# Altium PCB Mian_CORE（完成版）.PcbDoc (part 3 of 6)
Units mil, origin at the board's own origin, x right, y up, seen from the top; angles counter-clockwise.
Board outline 2755.91 x 1771.65 mil, 4 copper layers (TOP, GND02, PWR03, BOTTOM); 61 components, 130 nets, 4907 pads, 497 vias.
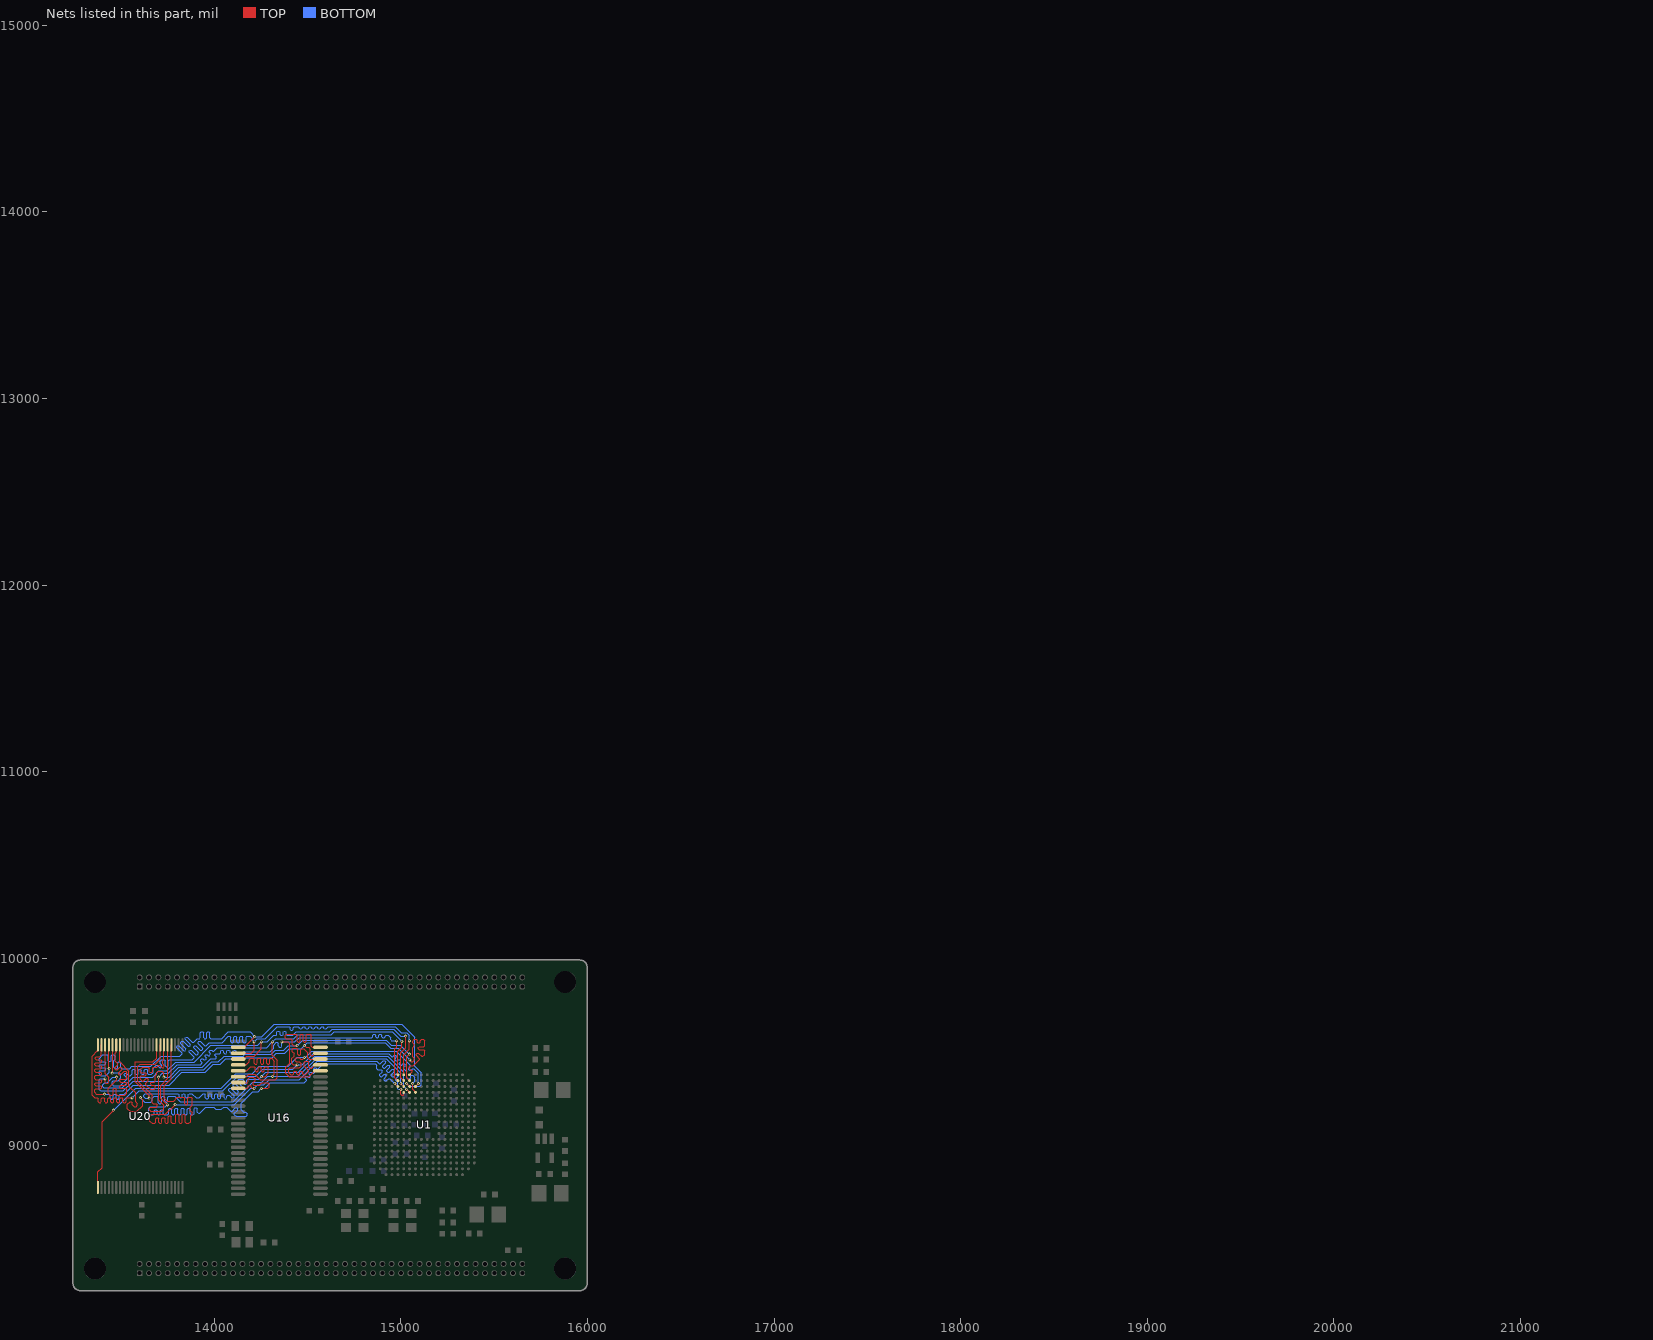
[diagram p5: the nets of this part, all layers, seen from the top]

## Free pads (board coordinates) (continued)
  round 8 on Drill Drawing: 1(18151.23,8951.1) 1(18151.23,8951.1) 1(18151.23,9026.1) 1(18151.23,9026.1) 1(18169.89,8951.1) 1(18169.89,8951.1) 1(18169.89,9026.1) 1(18169.89,9026.1) 1(18177.36,8954.85) 1(18177.36,8954.85) 1(18177.36,9022.35) 1(18177.36,9022.35) 1(18182.96,8959.85) 1(18182.96,8959.85) 1(18182.96,9017.35) 1(18182.96,9017.35) 1(18187.63,8967.35) 1(18187.63,8967.35) 1(18187.63,9009.85) 1(18187.63,9009.85) 1(18191.36,8976.1) 1(18191.36,8976.1) 1(18191.36,9001.1) 1(18191.36,9001.1) 1(18192.29,8988.6) 1(18192.29,8988.6) 1(18235.56,8951.1) 1(18235.56,9026.1) 1(18246.76,8951.1) 1(18246.76,9026.1) 1(18257.96,8951.1) 1(18257.96,9026.1) 1(18304.03,8951.1) 1(18304.03,8989.85) 1(18304.03,9026.1) 1(18304.03,9026.1) 1(18326.43,8989.85) 1(18339.49,9026.1) 1(18352.8,9563.73) 1(18356.53,9609.98) 1(18356.53,9609.98) 1(18358.4,9618.73) 1(18358.4,9618.73) 1(18359.33,9601.23) 1(18359.33,9601.23) 1(18360.27,9557.48) 1(18360.27,9557.48) 1(18363.07,9624.98) 1(18363.07,9624.98) 1(18365.87,9596.23) 1(18365.87,9596.23) 1(18368.67,9553.73) 1(18368.67,9553.73) 1(18369.6,9628.73) 1(18369.6,9628.73) 1(18376.13,9553.73) 1(18376.13,9553.73) 1(18376.13,9628.73) 1(18376.13,9628.73) 1(18377.07,9593.73) 1(18377.07,9593.73) 1(18379.03,8951.1) 1(18379.03,8989.85) 1(18379.03,9026.1) 1(18379.03,9026.1) 1(18382.67,9626.23) 1(18382.67,9626.23) 1(18383.6,9557.48) 1(18383.6,9557.48) 1(18385.47,9588.73) 1(18385.47,9588.73) 1(18388.27,9619.98) 1(18389.2,9563.73) 1(18389.2,9563.73) 1(18390.13,9581.23) 1(18390.13,9581.23) 1(18392,9572.48) 1(18392,9572.48) 1(18401.43,8989.85) 1(18414.49,9026.1) 1(18436.2,9553.73) 1(18436.2,9628.73) 1(18447.4,9553.73) 1(18447.4,9628.73) 1(18453.09,8951.1) 1(18453.09,8951.1) 1(18453.09,8989.85) 1(18453.09,9026.1) 1(18453.09,9026.1) 1(18458.6,9553.73) 1(18458.6,9628.73) 1(18475.49,8989.85) 1(18490.43,8951.1) 1(18490.43,9026.1) 1(18500.93,9553.73) 1(18500.93,9628.73) 1(18500.93,9628.73) 1(18528.09,8951.1) 1(18528.09,8987.35) 1(18528.09,9026.1) 1(18528.09,9026.1) 1(18543.87,9553.73) 1(18543.87,9553.73) 1(18543.87,9628.73) 1(18551.43,8987.35) 1(18551.43,8987.35) 1(18551.43,8987.35) 1(18551.43,9026.1) 1(18551.43,9026.1) 1(18557.96,8991.1) 1(18557.96,8991.1) 1(18558.89,9022.35) 1(18558.89,9022.35) 1(18563.56,8997.35) 1(18563.56,8997.35) 1(18563.56,9017.35) 1(18563.56,9017.35) 1(18565.43,8951.1) 1(18565.43,9007.35) 1(18565.43,9007.35) 1(18573.13,9587.48) 1(18573.13,9587.48) 1(18573.13,9596.23) 1(18573.13,9596.23) 1(18575,9577.48) 1(18575,9577.48) 1(18575,9603.73) 1(18575,9603.73) 1(18578.73,9568.73) 1(18578.73,9568.73) 1(18578.73,9612.48) 1(18578.73,9612.48) 1(18584.33,9561.23) 1(18584.33,9561.23) 1(18584.33,9619.98) 1(18584.33,9619.98) 1(18589.93,9624.98) 1(18589.93,9624.98) 1(18590.87,9556.23) 1(18590.87,9556.23) 1(18597.4,9628.73) 1(18597.4,9628.73) 1(18600.2,9553.73) 1(18600.2,9553.73) 1(18603,9591.23) 1(18603.09,8951.1) 1(18603.09,8951.1) 1(18603.09,8989.85) 1(18603.09,9026.1) 1(18603.09,9026.1) 1(18603.93,9628.73) 1(18603.93,9628.73) 1(18609.53,9556.23) 1(18609.53,9556.23) 1(18611.4,9626.23) 1(18611.4,9626.23) 1(18616.07,9561.23) 1(18616.07,9561.23) 1(18617,9621.23) 1(18621.67,9568.73) 1(18621.67,9568.73) 1(18621.67,9591.23) 1(18621.67,9591.23) 1(18625.49,8989.85) 1(18640.43,8951.1) 1(18640.43,9026.1) 1(18653.73,9553.73) 1(18653.73,9553.73) 1(18653.73,9628.73) 1(18675.29,8951.1) 1(18675.29,9026.1) 1(18675.29,9026.1) 1(18691.07,9553.73) 1(18718.23,8951.1) 1(18718.23,8951.1) 1(18718.23,9026.1) 1(18728.73,9553.73) 1(18728.73,9553.73) 1(18728.73,9592.48) 1(18728.73,9628.73) 1(18728.73,9628.73) 1(18750.29,9026.1) 1(18751.13,9592.48) 1(18766.07,9553.73) 1(18766.07,9628.73) 1(18771.76,8951.1) 1(18771.76,9026.1) 1(18793.23,9026.1) 1(18835.56,9026.1) 1(18846.76,8951.1) 1(18846.76,9026.1) 1(18857.96,9026.1) 1(18875.93,9628.73) 1(18897.37,8938.89) 1(18897.4,9553.73) 1(18897.4,9628.73) 1(18898.43,8951.1) 1(18906.83,8977.35) 1(18918.87,9628.73) 1(18919.77,8938.89) 1(18921.76,9026.1) 1(18921.76,9026.1) 1(18936.69,8977.35) 1(18945.09,8951.1) 1(18953.73,9553.73) 1(18953.73,9589.98) 1(18953.73,9628.73) 1(18953.73,9628.73) 1(18977.07,9589.98) 1(18977.07,9589.98) 1(18977.07,9589.98) 1(18977.07,9628.73) 1(18977.07,9628.73) 1(18978.09,8951.1) 1(18978.09,8951.1) 1(18978.09,9026.1) 1(18983.6,9593.73) 1(18983.6,9593.73) 1(18984.53,9624.98) 1(18984.53,9624.98) 1(18989.2,9599.98) 1(18989.2,9599.98) 1(18989.2,9619.98) 1(18989.2,9619.98) 1(18991.07,9553.73) 1(18991.07,9609.98) 1(18991.07,9609.98) 1(19015.43,8951.1) 1(19024.07,9553.73) 1(19032.47,9579.98) 1(19047.4,9628.73) 1(19047.4,9628.73) 1(19062.33,9579.98) 1(19070.73,9553.73) 1(19099.07,9587.48) 1(19099.07,9587.48) 1(19100,9598.73) 1(19100,9598.73) 1(19100.93,9576.23) 1(19100.93,9576.23) 1(19103.73,9568.73) 1(19103.73,9568.73) 1(19103.73,9611.23) 1(19103.73,9611.23) 1(19108.4,9618.73) 1(19108.4,9618.73) 1(19109.33,9561.23) 1(19109.33,9561.23) 1(19114.93,9624.98) 1(19114.93,9624.98) 1(19115.87,9556.23) 1(19115.87,9556.23) 1(19122.4,9553.73) 1(19122.4,9553.73) 1(19123.33,9628.73) 1(19123.33,9628.73) 1(19125.29,9026.1) 1(19128.93,9553.73) 1(19128.93,9553.73) 1(19130.8,9628.73) 1(19130.8,9628.73) 1(19135.47,9556.23) 1(19135.47,9556.23) 1(19137.33,9626.23) 1(19137.33,9626.23) 1(19141.07,9559.98) 1(19141.07,9559.98) 1(19142.93,9622.48) 1(19145.73,9564.98) 1(19146.76,8951.1) 1(19146.76,9026.1) 1(19168.23,9026.1) 1(19178.73,9553.73) 1(19178.73,9553.73) 1(19178.73,9592.48) 1(19178.73,9628.73) 1(19178.73,9628.73) 1(19201.13,9592.48) 1(19203.09,8951.1) 1(19203.09,8987.35) 1(19203.09,9026.1) 1(19203.09,9026.1) 1(19216.07,9553.73) 1(19216.07,9628.73) 1(19226.43,8987.35) 1(19226.43,8987.35) 1(19226.43,8987.35) 1(19226.43,9026.1) 1(19226.43,9026.1) 1(19232.96,8991.1) 1(19232.96,8991.1) 1(19233.89,9022.35) 1(19233.89,9022.35) 1(19238.56,8997.35) 1(19238.56,8997.35) 1(19238.56,9017.35) 1(19238.56,9017.35) 1(19240.43,8951.1) 1(19240.43,9007.35) 1(19240.43,9007.35) 1(19273.43,8951.1) 1(19281.83,8977.35) 1(19296.76,9026.1) 1(19296.76,9026.1) 1(19311.69,8977.35) 1(19320.09,8951.1) 1(19336.2,9553.73) 1(19336.2,9628.73) 1(19347.4,9553.73) 1(19347.4,9628.73) 1(19348.43,8984.85) 1(19348.43,8984.85) 1(19349.36,8996.1) 1(19349.36,8996.1) 1(19350.29,8973.6) 1(19350.29,8973.6) 1(19353.09,8966.1) 1(19353.09,8966.1) 1(19353.09,9008.6) 1(19353.09,9008.6) 1(19357.76,9016.1) 1(19357.76,9016.1) 1(19358.6,9553.73) 1(19358.6,9628.73) 1(19358.69,8958.6) 1(19358.69,8958.6) 1(19364.29,9022.35) 1(19364.29,9022.35) 1(19365.23,8953.6) 1(19365.23,8953.6) 1(19371.76,8951.1) 1(19371.76,8951.1) 1(19372.69,9026.1) 1(19372.69,9026.1) 1(19378.29,8951.1) 1(19378.29,8951.1) 1(19380.16,9026.1) 1(19380.16,9026.1) 1(19384.83,8953.6) 1(19384.83,8953.6) 1(19386.69,9023.6) 1(19386.69,9023.6) 1(19390.43,8957.35) 1(19390.43,8957.35) 1(19392.29,9019.85) 1(19395.09,8962.35) 1(19398.13,9553.73) 1(19398.13,9628.73) 1(19398.13,9628.73) 1(19422.4,9566.23) 1(19422.4,9566.23) 1(19428.09,8951.1) 1(19428.09,8951.1) 1(19428.09,8989.85) 1(19428.09,9026.1) 1(19428.09,9026.1) 1(19446.67,9553.73) 1(19446.67,9628.73) 1(19446.67,9628.73) 1(19450.49,8989.85) 1(19465.43,8951.1) 1(19465.43,9026.1) 1(19478.73,9553.73) 1(19478.73,9584.98) 1(19478.73,9628.73) 1(19478.73,9628.73) 1(19501.13,9584.98) 1(19501.13,9584.98) 1(19501.13,9628.73) 1(19501.13,9628.73) 1(19508.6,9624.98) 1(19508.6,9624.98) 1(19509.53,9588.73) 1(19509.53,9588.73) 1(19514.2,9596.23) 1(19514.2,9596.23) 1(19514.2,9616.23) 1(19514.2,9616.23) 1(19516.07,9606.23) 1(19516.07,9606.23) 1(19553.73,9553.73) 1(19553.73,9553.73) 1(19553.73,9592.48) 1(19553.73,9628.73) 1(19553.73,9628.73) 1(19576.13,9592.48) 1(19585.56,8951.1) 1(19585.56,9026.1) 1(19591.07,9553.73) 1(19591.07,9628.73) 1(19596.76,8951.1) 1(19596.76,9026.1) 1(19607.96,8951.1) 1(19607.96,9026.1) 1(19626.87,9553.73) 1(19626.87,9553.73) 1(19626.87,9628.73) 1(19626.87,9628.73) 1(19645.53,9553.73) 1(19645.53,9553.73) 1(19645.53,9628.73) 1(19645.53,9628.73) 1(19647.49,8951.1) 1(19647.49,9026.1) 1(19647.49,9026.1) 1(19653,9557.48) 1(19653,9557.48) 1(19653,9624.98) 1(19653,9624.98) 1(19658.6,9562.48) 1(19658.6,9562.48) 1(19658.6,9619.98) 1(19658.6,9619.98) 1(19663.27,9569.98) 1(19663.27,9569.98) 1(19663.27,9612.48) 1(19663.27,9612.48) 1(19667,9578.73) 1(19667,9578.73) 1(19667,9603.73) 1(19667,9603.73) 1(19667.93,9591.23) 1(19667.93,9591.23) 1(19671.76,8963.6) 1(19671.76,8963.6) 1(19696.03,8951.1) 1(19696.03,9026.1) 1(19696.03,9026.1) 1(19699.07,9553.73) 1(19707.47,9579.98) 1(19722.4,9628.73) 1(19722.4,9628.73) 1(19728.09,8951.1) 1(19728.09,8982.35) 1(19728.09,9026.1) 1(19728.09,9026.1) 1(19737.33,9579.98) 1(19745.73,9553.73) 1(19750.49,8982.35) 1(19750.49,8982.35) 1(19750.49,9026.1) 1(19750.49,9026.1) 1(19757.96,9022.35) 1(19757.96,9022.35) 1(19758.89,8986.1) 1(19758.89,8986.1) 1(19763.56,8993.6) 1(19763.56,8993.6) 1(19763.56,9013.6) 1(19763.56,9013.6) 1(19765.43,9003.6) 1(19765.43,9003.6) 1(19775.93,9553.73) 1(19775.93,9628.73) 1(19775.93,9628.73) 1(19803.09,8951.1) 1(19803.09,8951.1) 1(19803.09,8989.85) 1(19803.09,9026.1) 1(19803.09,9026.1) 1(19818.87,9553.73) 1(19818.87,9553.73) 1(19818.87,9628.73) 1(19825.49,8989.85) 1(19840.43,8951.1) 1(19840.43,9026.1) 1(19849.07,9587.48) 1(19849.07,9587.48) 1(19850,9598.73) 1(19850,9598.73) 1(19850.93,9576.23) 1(19850.93,9576.23) 1(19853.73,9568.73) 1(19853.73,9568.73) 1(19853.73,9611.23) 1(19853.73,9611.23) 1(19858.4,9618.73) 1(19858.4,9618.73) 1(19859.33,9561.23) 1(19859.33,9561.23) 1(19864.93,9624.98) 1(19864.93,9624.98) 1(19865.87,9556.23) 1(19865.87,9556.23) 1(19872.4,9553.73) 1(19872.4,9553.73) 1(19873.33,9628.73) 1(19873.33,9628.73) 1(19876.23,8951.1) 1(19876.23,8951.1) 1(19876.23,9026.1) 1(19876.23,9026.1) 1(19878.93,9553.73) 1(19878.93,9553.73) 1(19880.8,9628.73) 1(19880.8,9628.73) 1(19885.47,9556.23) 1(19885.47,9556.23) 1(19887.33,9626.23) 1(19887.33,9626.23) 1(19891.07,9559.98) 1(19891.07,9559.98) 1(19892.93,9622.48) 1(19894.89,8951.1) 1(19894.89,8951.1) 1(19894.89,9026.1) 1(19894.89,9026.1) 1(19895.73,9564.98) 1(19902.36,8954.85) 1(19902.36,8954.85) 1(19902.36,9022.35) 1(19902.36,9022.35) 1(19907.96,8959.85) 1(19907.96,8959.85) 1(19907.96,9017.35) 1(19907.96,9017.35) 1(19912.63,8967.35) 1(19912.63,8967.35) 1(19912.63,9009.85) 1(19912.63,9009.85) 1(19916.36,8976.1) 1(19916.36,8976.1) 1(19916.36,9001.1) 1(19916.36,9001.1) 1(19917.29,8988.6) 1(19917.29,8988.6) 1(19928.73,9553.73) 1(19928.73,9553.73) 1(19928.73,9592.48) 1(19928.73,9628.73) 1(19928.73,9628.73) 1(19948.43,8951.1) 1(19951.13,9592.48) 1(19956.83,8977.35) 1(19966.07,9553.73) 1(19966.07,9628.73) 1(19971.76,9026.1) 1(19971.76,9026.1) 1(19986.69,8977.35) 1(19995.09,8951.1) 1(20025.29,8951.1) 1(20025.29,9026.1) 1(20025.29,9026.1) 1(20068.23,8951.1) 1(20068.23,8951.1) 1(20068.23,9026.1) 1(20074.07,9587.48) 1(20074.07,9587.48) 1(20075,9598.73) 1(20075,9598.73) 1(20075.93,9576.23) 1(20075.93,9576.23) 1(20078.73,9568.73) 1(20078.73,9568.73) 1(20078.73,9611.23) 1(20078.73,9611.23) 1(20083.4,9618.73) 1(20083.4,9618.73) 1(20084.33,9561.23) 1(20084.33,9561.23) 1(20089.93,9624.98) 1(20089.93,9624.98) 1(20090.87,9556.23) 1(20090.87,9556.23) 1(20097.4,9553.73) 1(20097.4,9553.73) 1(20098.33,9628.73) 1(20098.33,9628.73) 1(20098.43,8984.85) 1(20098.43,8984.85) 1(20099.36,8996.1) 1(20099.36,8996.1) 1(20100.29,8973.6) 1(20100.29,8973.6) 1(20103.09,8966.1) 1(20103.09,8966.1) 1(20103.09,9008.6) 1(20103.09,9008.6) 1(20103.93,9553.73) 1(20103.93,9553.73) 1(20105.8,9628.73) 1(20105.8,9628.73) 1(20107.76,9016.1) 1(20107.76,9016.1) 1(20108.69,8958.6) 1(20108.69,8958.6) 1(20110.47,9556.23) 1(20110.47,9556.23) 1(20112.33,9626.23) 1(20112.33,9626.23) 1(20114.29,9022.35) 1(20114.29,9022.35) 1(20115.23,8953.6) 1(20115.23,8953.6) 1(20116.07,9559.98) 1(20116.07,9559.98) 1(20117.93,9622.48) 1(20120.73,9564.98) 1(20121.76,8951.1) 1(20121.76,8951.1) 1(20122.69,9026.1) 1(20122.69,9026.1) 1(20128.29,8951.1) 1(20128.29,8951.1) 1(20130.16,9026.1) 1(20130.16,9026.1) 1(20134.83,8953.6) 1(20134.83,8953.6) 1(20136.69,9023.6) 1(20136.69,9023.6) 1(20140.43,8957.35) 1(20140.43,8957.35) 1(20142.29,9019.85) 1(20145.09,8962.35) 1(20147.2,9586.23) 1(20147.2,9586.23) 1(20147.2,9596.23) 1(20147.2,9596.23) 1(20149.07,9576.23) 1(20149.07,9576.23) 1(20149.07,9606.23) 1(20149.07,9606.23) 1(20152.8,9567.48) 1(20152.8,9567.48) 1(20152.8,9614.98) 1(20152.8,9614.98) 1(20158.4,9559.98) 1(20158.4,9559.98) 1(20158.4,9622.48) 1(20158.4,9622.48) 1(20164.93,9554.98) 1(20164.93,9554.98) 1(20164.93,9627.48) 1(20164.93,9627.48) 1(20172.4,9553.73) 1(20172.4,9553.73) 1(20172.4,9628.73) 1(20172.4,9628.73) 1(20178.09,8951.1) 1(20178.09,8951.1) 1(20178.09,8989.85) 1(20178.09,9026.1) 1(20178.09,9026.1) 1(20179.87,9554.98) 1(20179.87,9554.98) 1(20179.87,9627.48) 1(20179.87,9627.48) 1(20186.4,9559.98) 1(20186.4,9559.98) 1(20186.4,9622.48) 1(20186.4,9622.48) 1(20192,9567.48) 1(20192,9567.48) 1(20192,9614.98) 1(20192,9614.98) 1(20195.73,9576.23) 1(20195.73,9576.23) 1(20195.73,9606.23) 1(20195.73,9606.23) 1(20197.6,9586.23) 1(20197.6,9586.23) 1(20197.6,9596.23) 1(20197.6,9596.23) 1(20200.49,8989.85) 1(20215.43,8951.1) 1(20215.43,9026.1) 1(20225.93,9553.73) 1(20225.93,9628.73) 1(20225.93,9628.73) 1(20268.87,9553.73) 1(20268.87,9553.73) 1(20268.87,9628.73) 1(20300.93,9628.73) 1(20322.4,9553.73) 1(20322.4,9628.73) 1(20323.43,8984.85) 1(20323.43,8984.85) 1(20324.36,8996.1) 1(20324.36,8996.1) 1(20325.29,8973.6) 1(20325.29,8973.6) 1(20328.09,8966.1) 1(20328.09,8966.1) 1(20328.09,9008.6) 1(20328.09,9008.6) 1(20332.76,9016.1) 1(20332.76,9016.1) 1(20333.69,8958.6) 1(20333.69,8958.6) 1(20339.29,9022.35) 1(20339.29,9022.35) 1(20340.23,8953.6) 1(20340.23,8953.6) 1(20343.87,9628.73) 1(20346.76,8951.1) 1(20346.76,8951.1) 1(20347.69,9026.1) 1(20347.69,9026.1) 1(20353.29,8951.1) 1(20353.29,8951.1) 1(20355.16,9026.1) 1(20355.16,9026.1) 1(20359.83,8953.6) 1(20359.83,8953.6) 1(20361.69,9023.6) 1(20361.69,9023.6) 1(20365.43,8957.35) 1(20365.43,8957.35) 1(20367.29,9019.85) 1(20370.09,8962.35) 1(20378.73,9553.73) 1(20378.73,9589.98) 1(20378.73,9628.73) 1(20378.73,9628.73) 1(20396.56,8983.6) 1(20396.56,8983.6) 1(20396.56,8993.6) 1(20396.56,8993.6) 1(20398.43,8973.6) 1(20398.43,8973.6) 1(20398.43,9003.6) 1(20398.43,9003.6) 1(20402.07,9589.98) 1(20402.07,9589.98) 1(20402.07,9589.98) 1(20402.07,9628.73) 1(20402.07,9628.73) 1(20402.16,8964.85) 1(20402.16,8964.85) 1(20402.16,9012.35) 1(20402.16,9012.35) 1(20407.76,8957.35) 1(20407.76,8957.35) 1(20407.76,9019.85) 1(20407.76,9019.85) 1(20408.6,9593.73) 1(20408.6,9593.73) 1(20409.53,9624.98) 1(20409.53,9624.98) 1(20414.2,9599.98) 1(20414.2,9599.98) 1(20414.2,9619.98) 1(20414.2,9619.98) 1(20414.29,8952.35) 1(20414.29,8952.35) 1(20414.29,9024.85) 1(20414.29,9024.85) 1(20416.07,9553.73) 1(20416.07,9609.98) 1(20416.07,9609.98) 1(20421.76,8951.1) 1(20421.76,8951.1) 1(20421.76,9026.1) 1(20421.76,9026.1) 1(20429.23,8952.35) 1(20429.23,8952.35) 1(20429.23,9024.85) 1(20429.23,9024.85) 1(20435.76,8957.35) 1(20435.76,8957.35) 1(20435.76,9019.85) 1(20435.76,9019.85) 1(20441.36,8964.85) 1(20441.36,8964.85) 1(20441.36,9012.35) 1(20441.36,9012.35) 1(20445.09,8973.6) 1(20445.09,8973.6) 1(20445.09,9003.6) 1(20445.09,9003.6) 1(20446.96,8983.6) 1(20446.96,8983.6) 1(20446.96,8993.6) 1(20446.96,8993.6) 1(20447.2,9586.23) 1(20447.2,9586.23) 1(20447.2,9596.23) 1(20447.2,9596.23) 1(20449.07,9576.23) 1(20449.07,9576.23) 1(20449.07,9606.23) 1(20449.07,9606.23) 1(20452.8,9567.48) 1(20452.8,9567.48) 1(20452.8,9614.98) 1(20452.8,9614.98) 1(20458.4,9559.98) 1(20458.4,9559.98) 1(20458.4,9622.48) 1(20458.4,9622.48) 1(20464.93,9554.98) 1(20464.93,9554.98) 1(20464.93,9627.48) 1(20464.93,9627.48) 1(20472.4,9553.73) 1(20472.4,9553.73) 1(20472.4,9628.73) 1(20472.4,9628.73) 1(20475.29,8951.1) 1(20475.29,9026.1) 1(20475.29,9026.1) 1(20479.87,9554.98) 1(20479.87,9554.98) 1(20479.87,9627.48) 1(20479.87,9627.48) 1(20486.4,9559.98) 1(20486.4,9559.98) 1(20486.4,9622.48) 1(20486.4,9622.48) 1(20492,9567.48) 1(20492,9567.48) 1(20492,9614.98) 1(20492,9614.98) 1(20495.73,9576.23) 1(20495.73,9576.23) 1(20495.73,9606.23) 1(20495.73,9606.23) 1(20497.6,9586.23) 1(20497.6,9586.23) 1(20497.6,9596.23) 1(20497.6,9596.23) 1(20518.23,8951.1) 1(20518.23,8951.1) 1(20518.23,9026.1) 1(20528.73,9553.73) 1(20528.73,9553.73) 1(20528.73,9628.73) 1(20550.29,9026.1) 1(20566.07,9553.73) 1(20571.76,8951.1) 1(20571.76,9026.1) 1(20593.23,9026.1) 1(20628.09,8951.1) 1(20628.09,8987.35) 1(20628.09,9026.1) 1(20628.09,9026.1) 1(20651.43,8987.35) 1(20651.43,8987.35) 1(20651.43,8987.35) 1(20651.43,9026.1) 1(20651.43,9026.1) 1(20657.96,8991.1) 1(20657.96,8991.1) 1(20658.89,9022.35) 1(20658.89,9022.35) 1(20663.56,8997.35) 1(20663.56,8997.35) 1(20663.56,9017.35) 1(20663.56,9017.35) 1(20665.43,8951.1) 1(20665.43,9007.35) 1(20665.43,9007.35) 1(20696.56,8983.6) 1(20696.56,8983.6) 1(20696.56,8993.6) 1(20696.56,8993.6) 1(20698.43,8973.6) 1(20698.43,8973.6) 1(20698.43,9003.6) 1(20698.43,9003.6) 1(20702.16,8964.85) 1(20702.16,8964.85) 1(20702.16,9012.35) 1(20702.16,9012.35) 1(20707.76,8957.35) 1(20707.76,8957.35) 1(20707.76,9019.85) 1(20707.76,9019.85) 1(20714.29,8952.35) 1(20714.29,8952.35) 1(20714.29,9024.85) 1(20714.29,9024.85) 1(20721.76,8951.1) 1(20721.76,8951.1) 1(20721.76,9026.1) 1(20721.76,9026.1) 1(20729.23,8952.35) 1(20729.23,8952.35) 1(20729.23,9024.85) 1(20729.23,9024.85) 1(20735.76,8957.35) 1(20735.76,8957.35) 1(20735.76,9019.85) 1(20735.76,9019.85) 1(20741.36,8964.85) 1(20741.36,8964.85) 1(20741.36,9012.35) 1(20741.36,9012.35) 1(20745.09,8973.6) 1(20745.09,8973.6) 1(20745.09,9003.6) 1(20745.09,9003.6) 1(20746.96,8983.6) 1(20746.96,8983.6) 1(20746.96,8993.6) 1(20746.96,8993.6) 1(20778.09,8951.1) 1(20778.09,8951.1) 1(20778.09,9026.1) 1(20815.43,8951.1)
  round 11.8 on Drill Drawing: 1(18180.73,13438.42) 1(18180.73,13438.42) 1(18180.73,13528.18) 1(18180.73,13528.18) 1(18180.74,12990.28) 1(18180.74,12990.28) 1(18180.74,13080.04) 1(18180.74,13080.04) 1(18180.74,13940.28) 1(18180.74,13940.28) 1(18180.74,14030.04) 1(18180.74,14030.04) 1(18270.49,13438.42) 1(18270.49,13438.42) 1(18270.49,13528.18) 1(18270.49,13528.18) 1(18270.5,12990.28) 1(18270.5,12990.28) 1(18270.5,13080.04) 1(18270.5,13080.04) 1(18270.5,13940.28) 1(18270.5,13940.28) 1(18270.5,14030.04) 1(18270.5,14030.04) 1(18855.94,13290.28) 1(18855.94,13290.28) 1(18855.94,13380.04) 1(18855.94,13380.04) 1(18856.72,14091.06) 1(18856.72,14091.06) 1(18856.72,14180.82) 1(18856.72,14180.82) 1(18945.71,13290.28) 1(18945.71,13290.28) 1(18945.71,13380.04) 1(18945.71,13380.04) 1(18946.49,14091.06) 1(18946.49,14091.06) 1(18946.49,14180.82) 1(18946.49,14180.82) 1(19483.52,14542.42) 1(19483.52,14542.42) 1(19483.52,14632.18) 1(19483.52,14632.18) 1(19573.28,14542.42) 1(19573.28,14542.42) 1(19573.28,14632.18) 1(19573.28,14632.18) 1(20830.75,13140.28) 1(20830.75,13140.28) 1(20830.75,13230.04) 1(20830.75,13230.04) 1(20920.51,13140.28) 1(20920.51,13140.28) 1(20920.51,13230.04) 1(20920.51,13230.04)

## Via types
v1: diameter 16, hole 8, TOP to BOTTOM, tented both sides, 497 vias

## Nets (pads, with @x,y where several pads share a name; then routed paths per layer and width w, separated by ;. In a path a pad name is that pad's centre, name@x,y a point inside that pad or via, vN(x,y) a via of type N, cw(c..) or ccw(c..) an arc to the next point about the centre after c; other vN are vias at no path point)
A0: U1.L3 U16.23 U20.25 | length 2934.4
  TOP w5.5: U20.25@13376.62,8773.11 13376.62,8855.62 13400,8879 13400,9126 v1(13461,9187) ; v1(14483.46,9469.46) 14473.99,9460 14464,9460 14457,9467 14440,9467 14435,9462 14435,9451 14439,9447 14455,9447 14466,9436 14466,9422 14457,9413 14404,9413 14399,9408 14399,9387 14409,9377 14420.3,9377 14425.25,9381.95 14425.25,9390.05 14430.2,9395 14436.8,9395 14441.75,9390.05 14441.75,9381.95 14446.7,9377 14453.3,9377 14458.25,9381.95 14458.25,9390.05 14463.2,9395 14469.8,9395 14474.75,9390.05 14474.75,9381.95 14479.7,9377 14487,9377 14503.16,9393.16 14503.16,9400.16 14481.88,9421.45 14481.88,9442.88 14489,9450 14500,9450 14506,9444 14506,9420.66 14514.83,9411.83 14521.83,9411.83 14539.46,9429.46 U16.23@14569.47,9429.46 ; U1.L3@15078.76,9313.72 v1(15094.5,9329.47)
  BOTTOM w5.5: v1(13461,9187) 13579,9305 14037,9305 14115,9383 14203,9383 14242,9422 14397,9422 14444.46,9469.46 v1(14483.46,9469.46) 14489.46,9469.46 14522.94,9502.94 14975.06,9502.94 15051.03,9426.97 15051.03,9419.97 15042.48,9411.41 15042.48,9404.41 15047.14,9399.74 15054.14,9399.74 15062.7,9408.3 15069.7,9408.3 15094.5,9383.5 v1(15094.5,9329.47)
A1: U1.L4 U16.24 U20.24 | length 2956.1
  TOP w5.5: U20.24@13376.62,9536.89 13376.62,9506.62 13346,9476 13346,9267 13360,9253 13374.3,9253 13379.25,9248.05 13379.25,9231.95 13384.2,9227 13390.8,9227 13395.75,9231.95 13395.75,9248.05 13400.7,9253 13407.3,9253 13412.25,9248.05 13412.25,9231.95 13417.2,9227 13423.8,9227 13428.75,9231.95 13428.75,9248.05 13433.7,9253 13440.3,9253 13445.25,9248.05 13445.25,9231.95 13450.2,9227 13456.8,9227 13461.75,9231.95 13461.75,9248.05 13466.7,9253 13473.3,9253 13478.25,9248.05 13478.25,9231.95 13483.2,9227 13489.8,9227 13494.75,9231.95 13494.75,9248.05 13499.7,9253 13506.3,9253 13511.25,9248.05 13511.25,9231.95 13516.2,9227 13522.8,9227 13527.75,9231.95 13527.75,9248.05 13532.7,9253 v1(13560,9253) ; v1(14445,9430.01) 14423.99,9430.01 14416,9438 14416,9464 14428,9476 14428,9491 14418,9501 14418,9513 14423,9518 14439.3,9518 14447.25,9510.05 14447.25,9485.25 14452.2,9480.3 14458.8,9480.3 14463.75,9485.25 14463.75,9510.05 14468.7,9515 14481,9515 14502,9494 14502,9467 14508.04,9460.96 U16.24@14569.47,9460.96 ; v1(15063.01,9329.47) 15063.01,9297.98 U1.L4@15078.76,9282.23
  BOTTOM w5.5: v1(13560,9253) 13598,9291 14047,9291 14125,9369 14223,9369 14260,9406 14420.99,9406 v1(14445,9430.01) 14472.01,9430.01 14532,9490 14935,9490 14950.89,9474.11 14957.89,9474.11 14965.03,9481.25 14972.03,9481.25 14976.7,9476.59 14976.7,9469.58 14969.56,9462.44 14969.56,9455.44 14974.22,9450.78 14981.22,9450.78 14988.37,9457.92 14995.37,9457.92 15000.03,9453.25 15000.03,9446.25 14992.89,9439.11 14992.89,9432.11 14997.56,9427.44 15004.56,9427.44 15011.7,9434.58 15018.7,9434.58 15023.37,9429.92 15023.37,9422.92 15016.23,9415.77 15016.23,9408.77 15031,9394 15031,9361.48 15036.48,9356 15048,9356 15052,9360 15052,9370 15056,9374 15065,9374 15076,9363 15076,9342.46 v1(15063.01,9329.47)
A2: U1.M1 U16.25 U20.23 | length 3235.9
  TOP w5.5: U20.23@13396.06,9536.64 13396.06,9483.81 13386,9473.75 13368.51,9473.75 13363.56,9468.8 13363.56,9462.2 13368.51,9457.25 13391.36,9457.25 13396.31,9452.3 13396.31,9445.7 13391.36,9440.75 13365.26,9440.75 13360.31,9435.8 13360.31,9429.2 13365.26,9424.25 13391.36,9424.25 13396.31,9419.3 13396.31,9412.7 13391.36,9407.75 13365.26,9407.75 13360.31,9402.8 13360.31,9396.2 13365.26,9391.25 13391.36,9391.25 13396.31,9386.3 13396.31,9379.7 13391.36,9374.75 13365.26,9374.75 13360.31,9369.8 13360.31,9355.7 13365.26,9350.75 13391.36,9350.75 13396.31,9345.8 13396.31,9339.2 13391.36,9334.25 13365.26,9334.25 13360.31,9329.3 13360.31,9322.7 13365.26,9317.75 13391.36,9317.75 13396.31,9312.8 13396.31,9306.2 13391.36,9301.25 13365.26,9301.25 13360.31,9296.3 13360.31,9281.69 13369,9273 v1(13413,9273) ; v1(14483.46,9532.46) 14492.46,9523.46 14505.54,9523.46 14515.96,9513.04 14515.96,9484.04 14521,9479 14529,9479 14542.46,9492.46 U16.25@14569.47,9492.46 ; U1.M1@15047.26,9376.72 15062.27,9391.73 15062.27,9397.73 15058,9402 15052,9402 15045,9409 15045,9420 15050,9425 15068,9425 15099.33,9456.33 15099.33,9463.33 15082.29,9480.38 15082.29,9487.38 15086.96,9492.04 15093.96,9492.04 15111,9475 15118,9475 15127,9484 15127,9506.3 15122.05,9511.25 15097.95,9511.25 15093,9516.2 15093,9522.8 15097.95,9527.75 15122.05,9527.75 15127,9532.7 15127,9558 15119,9566 15112,9566 15105,9559 15105,9552 15101,9548 15091,9548 15087,9552 15087,9562 15083,9566 15073,9566 15064,9557 15064,9547 15073,9538 15073,9531 15064,9522 15064,9473 15071,9466 15071,9454 15063,9446 15056.52,9446 15047.26,9455.26 v1(15048,9456)
  BOTTOM w5.5: v1(13413,9273) 13437.3,9273 13442.25,9268.05 13442.25,9249.95 13447.2,9245 13453.8,9245 13458.75,9249.95 13458.75,9268.05 13463.7,9273 13470.3,9273 13475.25,9268.05 13475.25,9249.95 13480.2,9245 13486.8,9245 13491.75,9249.95 13491.75,9268.05 13496.7,9273 13519,9273 13567,9321 13758,9321 13826,9389 13952,9389 13995.67,9432.67 14032.67,9432.67 14062,9462 14164,9462 14170,9468 14310,9468 14332.95,9490.95 14377.95,9490.95 14402,9515 14466,9515 v1(14483.46,9532.46) 14499,9548 14917,9548 14947.02,9517.98 14986.02,9517.98 v1(15048,9456)
A3: U1.M2 U16.26 U20.22 | length 2812.4
  TOP w5.5: v1@13415.99,9354.99 v1(13415,9354) 13415,9337 13420,9332 13432,9332 13436,9336 13436,9362 13415.99,9382.01 U20.22@13415.99,9536.89 ; v1(14445,9533) 14425,9533 14418,9540 14418,9562 14411,9569 14387,9569 14382,9574 14382,9587 14388,9593 14439.3,9593 14444.25,9588.05 14444.25,9555.95 14449.2,9551 14455.8,9551 14460.75,9555.95 14460.75,9588.05 14465.7,9593 14472.3,9593 14477.25,9588.05 14477.25,9555.95 14482.2,9551 14488.8,9551 14493.75,9555.95 14493.75,9588.05 14498.7,9593 14514,9593 14520,9587 14520,9530 14526.05,9523.95 U16.26@14569.47,9523.95 ; v1(15046,9486.95) 15031.51,9472.46 15031.51,9360.97 U1.M2@15047.26,9345.22
  BOTTOM w5.5: v1(13415,9354) 13389,9354 13384,9349 13384,9297 13391,9290 13513,9290 13565,9342 13757,9342 13818,9403 13944,9403 13987,9446 14023,9446 14053,9476 14155,9476 14165,9486 14305,9486 14328,9509 14373,9509 14397,9533 v1(14445,9533) 14474,9562 14923,9562 14950,9535 14997.95,9535 v1(15046,9486.95) ; v1@15041.79,9486.95 v1(15046,9486.95) ; v1@15051.25,9486.95 v1(15046,9486.95)
A4: U1.M3 U16.29 U20.21 | length 3329.1
  TOP w5.5: U20.21@13435.68,9536.89 13435.68,9411.32 v1(13437,9410) ; U16.29@14128.53,9523.95 14159.95,9523.95 v1(14217,9581) ; v1(15031.51,9329.47) U1.M3@15047.26,9313.72
  BOTTOM w5.5: v1(13437,9410) 13437,9391 13418,9372 13392,9372 13383,9381 13383,9392.3 13387.95,9397.25 13414.05,9397.25 13419,9402.2 13419,9408.8 13414.05,9413.75 13387.95,9413.75 13383,9418.7 13383,9425.3 13387.95,9430.25 13414.05,9430.25 13419,9435.2 13419,9441.8 13414.05,9446.75 13387.95,9446.75 13383,9451.7 13383,9463 13404,9484 13426.3,9484 13431.25,9479.05 13431.25,9452.95 13436.2,9448 13442.8,9448 13447.75,9452.95 13447.75,9479.05 13452.7,9484 13463,9484 13471,9476 13471,9460 13463,9452 13463,9416 13469,9410 13478.3,9410 13483.25,9414.95 13483.25,9441.05 13488.2,9446 13494.8,9446 13499.75,9441.05 13499.75,9414.95 13504.7,9410 13547,9410 13558,9421 13661,9421 13716,9476 13815,9476 13825.36,9486.36 13825.36,9493.36 13798.42,9520.3 13798.42,9527.3 13803.08,9531.96 13810.08,9531.96 13837.02,9505.02 13844.02,9505.02 13848.69,9509.69 13848.69,9516.69 13821.75,9543.63 13821.75,9550.63 13826.42,9555.3 13833.42,9555.3 13860.36,9528.36 13867.36,9528.36 13872.03,9533.03 13872.03,9540.03 13845.08,9566.97 13845.08,9573.97 13849.75,9578.63 13856.75,9578.63 13883.69,9551.69 13890.69,9551.69 13909,9570 13921.3,9570 13926.25,9574.95 13926.25,9601.05 13931.2,9606 13937.8,9606 13942.75,9601.05 13942.75,9574.95 13947.7,9570 13954.3,9570 13959.25,9574.95 13959.25,9601.05 13964.2,9606 13970.8,9606 13975.75,9601.05 13975.75,9574.95 13980.7,9570 14040,9570 14076,9606 14192,9606 v1(14217,9581) 14256,9581 14323,9648 15005,9648 15075,9578 15075,9423 15110,9388 15110,9322 15101.72,9313.72 15047.26,9313.72 v1(15031.51,9329.47)
A5: U1.N1 U16.30 U20.20 | length 3206.6
  TOP w5.5: v1(13453,9386) 13455.36,9388.36 U20.20@13455.36,9536.89 ; U16.30@14128.53,9492.46 14198.46,9492.46 14214.54,9508.54 v1(14214.54,9552.46) ; U1.N1@15015.76,9376.72 15015.76,9483.76 15046,9514 v1(15046,9558)
  BOTTOM w5.5: v1@13454,9387 13490,9387 13500,9377 13500,9360 13485,9345 13458,9345 13453,9340 13453,9325 13459,9319 13496.3,9319 13530.94,9353.64 13530.94,9360.64 13518.14,9373.44 13518.14,9380.44 13522.81,9385.11 13529.81,9385.11 13542.61,9372.31 13549.61,9372.31 13560.25,9382.95 13560.25,9401.05 13565.2,9406 13571.8,9406 13576.75,9401.05 13576.75,9382.95 13581.7,9378 13588.3,9378 13593.25,9382.95 13593.25,9401.05 13598.2,9406 13604.8,9406 13609.75,9401.05 13609.75,9382.95 13614.7,9378 13621.3,9378 13626.25,9382.95 13626.25,9401.05 13631.2,9406 13637.8,9406 13642.75,9401.05 13642.75,9382.95 13647.7,9378 13664,9378 13674,9388 13674,9412 13688.83,9426.83 13695.83,9426.83 13707.66,9415 13714.66,9415 13719.32,9419.67 13719.32,9426.67 13707.49,9438.49 13707.49,9445.49 13719,9457 13732.3,9457 13737.25,9452.05 13737.25,9423.95 13742.2,9419 13748.8,9419 13753.75,9423.95 13753.75,9452.05 13758.7,9457 13882,9457 13890.83,9465.83 13890.83,9472.83 13866.72,9496.95 13866.72,9503.95 13871.39,9508.61 13878.39,9508.61 13902.5,9484.5 13909.5,9484.5 13914.17,9489.17 13914.17,9496.17 13890.06,9520.28 13890.06,9527.28 13894.72,9531.95 13901.72,9531.95 13925.84,9507.84 13932.84,9507.84 13937.5,9512.5 13937.5,9519.5 13913.39,9543.62 13913.39,9550.62 13918.06,9555.28 13925.06,9555.28 13949.17,9531.17 13956.17,9531.17 13974,9549 14042,9549 14076,9583 14083.3,9583 14088.25,9578.05 14088.25,9553.95 14093.2,9549 14099.8,9549 14104.75,9553.95 14104.75,9578.05 14109.7,9583 14116.3,9583 14121.25,9578.05 14121.25,9553.95 14126.2,9549 14132.8,9549 14137.75,9553.95 14137.75,9578.05 14142.7,9583 14149.3,9583 14154.25,9578.05 14154.25,9553.95 14159.2,9549 14165.8,9549 14170.75,9553.95 14170.75,9578.05 14175.7,9583 14193,9583 14203.5,9572.5 14203.5,9563.5 v1(14214.54,9552.46) 14231.09,9569 14273,9569 14338,9634 14401.3,9634 14406.25,9629.05 14406.25,9620.95 14411.2,9616 14417.8,9616 14422.75,9620.95 14422.75,9629.05 14427.7,9634 14451.3,9634 14456.25,9629.05 14456.25,9626.95 14461.2,9622 14467.8,9622 14472.75,9626.95 14472.75,9629.05 14477.7,9634 14484.3,9634 14489.25,9629.05 14489.25,9626.95 14494.2,9622 14500.8,9622 14505.75,9626.95 14505.75,9629.05 14510.7,9634 14517.3,9634 14522.25,9629.05 14522.25,9626.95 14527.2,9622 14533.8,9622 14538.75,9626.95 14538.75,9629.05 14543.7,9634 14550.3,9634 14555.25,9629.05 14555.25,9626.95 14560.2,9622 14566.8,9622 14571.75,9626.95 14571.75,9629.05 14576.7,9634 14583.3,9634 14588.25,9629.05 14588.25,9626.95 14593.2,9622 14599.8,9622 14611.8,9634 14970,9634 15001.84,9602.16 15031.84,9602.16 15046,9588 v1(15046,9558)
A6: U1.N2 U16.31 U20.19 | length 3177.8
  TOP w5.5: U20.19@13475.05,9536.89 13475.05,9497 13469,9490.95 13469,9450 13482.78,9436.22 13482.78,9429.22 13468.36,9414.81 13468.36,9407.81 13473.03,9403.14 13480.03,9403.14 13494.44,9417.56 13501.44,9417.56 13506.11,9412.89 13506.11,9405.89 13487.65,9387.43 13487.65,9380.43 13492.32,9375.77 13499.32,9375.77 13517.78,9394.22 13524.78,9394.22 13531,9388 13531,9357.7 13526.05,9352.75 13499.95,9352.75 13495,9347.8 13495,9341.2 13499.95,9336.25 13526.05,9336.25 13531,9331.3 13531,9324.7 13526.05,9319.75 13499.95,9319.75 13495,9314.8 13495,9308.2 13499.95,9303.25 13526.05,9303.25 13531,9298.3 13531,9278 13521,9268 13479.7,9268 13474.75,9272.95 13474.75,9299.05 13469.8,9304 13463.2,9304 13458.25,9299.05 13458.25,9272.95 13453.3,9268 13441,9268 13432,9277 13432,9304 13477,9349 v1(13477,9364) ; U16.31@14128.53,9460.96 14158.96,9460.96 14175,9477 14215,9477 14253,9515 v1(14253,9552.46) ; U1.N2@15015.76,9345.22 15000.02,9360.97 15000.02,9495.02 15026,9521 v1(15026,9584)
  BOTTOM w5.5: v1(13477,9364) 13457,9364 13428,9335 13413,9335 13402,9324 13402,9313 13409,9306 13508,9306 13566,9364 13670,9364 13703,9397 13747,9397 13794,9444 13892,9444 13982,9534 14234.54,9534 v1(14253,9552.46) 14283.46,9552.46 14318,9587 14331.3,9587 14336.25,9591.95 14336.25,9606.05 14341.2,9611 14347.8,9611 14352.75,9606.05 14352.75,9591.95 14357.7,9587 14364.3,9587 14369.25,9591.95 14369.25,9606.05 14374.2,9611 14380.8,9611 14385.75,9606.05 14385.75,9591.95 14390.7,9587 14420,9587 14439,9606 14619,9606 14633,9620 14963,9620 14999,9584 v1(15026,9584)
A7: U1.N3 U16.32 U20.18 | length 2840.8
  TOP w5.5: U20.18@13494.73,9536.89 13494.73,9445 13543,9396.73 13543,9315 13579,9279 13579,9231 13588,9222 13588,9212 13582,9206 13572,9206 13561,9217 13561,9227 13555,9233 13549,9233 13535,9219 13535,9194 13549,9180 13585,9180 13616,9211 13616,9242 v1(13604,9254) ; U16.32@14128.53,9429.46 14172.46,9429.46 14189,9446 14189,9456 14197,9464 14210.3,9464 14215.25,9459.05 14215.25,9436.95 14220.2,9432 14226.8,9432 14231.75,9436.95 14231.75,9459.05 14236.7,9464 14243.3,9464 14248.25,9459.05 14248.25,9436.95 14253.2,9432 14259.8,9432 14264.75,9436.95 14264.75,9459.05 14269.7,9464 14276.3,9464 14281.25,9459.05 14281.25,9436.95 14286.2,9432 14292.8,9432 14297.75,9436.95 14297.75,9459.05 14302.7,9464 14309,9464 14323,9450 14323,9378 v1(14313,9368) ; v1(15000.02,9329.47) U1.N3@15015.76,9313.72
  BOTTOM w5.5: v1(13604,9254) 13628,9230 13659,9230 13668,9239 13668,9250 13679,9261 13696.3,9261 13701.25,9256.05 13701.25,9225.95 13706.2,9221 13712.8,9221 13717.75,9225.95 13717.75,9256.05 13722.7,9261 13729.3,9261 13734.25,9256.05 13734.25,9234.86 13739.2,9229.91 13745.8,9229.91 13750.75,9234.86 13750.75,9256.05 13755.7,9261 13789,9261 13818,9232 14103,9232 14207,9336 14255,9336 14287,9368 v1(14313,9368) 14451,9368 14546,9463 14923,9463 15000.02,9385.98 v1(15000.02,9329.47)
A8: U1.M4 U16.33 U20.8 | length 2972.2
  TOP w5.5: v1(13651,9252) 13651,9263 13576,9338 13576,9447 13577,9446 13671.58,9446 13691.58,9466 U20.8@13691.58,9536.89 ; U16.33@14128.53,9397.97 14173.97,9397.97 14196,9420 14214.3,9420 14219.25,9415.05 14219.25,9396.95 14224.2,9392 14230.8,9392 14235.75,9396.95 14235.75,9415.05 14240.7,9420 14247.3,9420 14252.25,9415.05 14252.25,9396.95 14257.2,9392 14263.8,9392 14268.75,9396.95 14268.75,9415.05 14273.7,9420 14287,9420 14291,9416 14291,9384 14274.02,9367.02 v1(14253,9367.02) ; v1(15031.51,9297.98) U1.M4@15047.26,9282.23
  BOTTOM w5.5: v1(13651,9252) 13630,9252 13622,9260 13622,9267 13631,9276 13807.3,9276 13812.25,9271.05 13812.25,9258.95 13817.2,9254 13823.8,9254 13828.75,9258.95 13828.75,9271.05 13833.7,9276 13840.3,9276 13845.25,9271.05 13845.25,9258.95 13850.2,9254 13856.8,9254 13861.75,9258.95 13861.75,9271.05 13866.7,9276 13880,9276 13903,9253 13921,9253 13942,9274 13948.3,9274 13953.25,9269.05 13953.25,9252.95 13958.2,9248 13964.8,9248 13969.75,9252.95 13969.75,9269.05 13974.7,9274 13981.3,9274 13986.25,9269.05 13986.25,9252.95 13991.2,9248 13997.8,9248 14002.75,9252.95 14002.75,9269.05 14007.7,9274 14014.3,9274 14019.25,9269.05 14019.25,9252.95 14024.2,9248 14030.8,9248 14035.75,9252.95 14035.75,9269.05 14040.7,9274 14048,9274 14053,9269 14053,9253 14057,9249 14064,9249 14068,9253 14068,9262 14073,9267 14080.13,9267 14094.92,9252.21 14101.92,9252.21 14106.59,9256.88 14106.59,9263.88 14078.23,9292.23 14078.23,9299.23 14082.9,9303.9 14089.9,9303.9 14118.25,9275.54 14125.25,9275.54 14129.92,9280.21 14129.92,9287.21 14101.57,9315.57 14101.57,9322.57 14106.23,9327.23 14113.23,9327.23 14141.59,9298.88 14148.59,9298.88 14153.26,9303.54 14153.26,9310.54 14124.9,9338.9 14124.9,9345.9 14132,9353 14152.3,9353 14157.25,9348.05 14157.25,9331.95 14162.2,9327 14168.8,9327 14173.75,9331.95 14173.75,9348.05 14178.7,9353 14238.98,9353 v1(14253,9367.02) 14274.98,9389 14450.59,9389 14538.59,9477 14929,9477 15015.76,9390.24 15015.76,9313.72 v1(15031.51,9297.98)
A9: U1.P1 U16.34 U20.7 | length 2921.9
  TOP w5.5: v1(13702,9364) 13702,9239 13729,9212 13729,9192 13719,9182 13659,9182 13653,9188 13653,9197 13659,9203 13690,9203 13694,9207 13694,9216 13689,9221 13673,9221 13667,9227 13667,9267 13591,9343 13591,9421 13603,9433 13685,9433 13711.27,9459.27 U20.7@13711.27,9536.89 ; U16.34@14128.53,9366.47 14171.47,9366.47 14185,9380 14216,9380 14246,9350 14328,9350 14338,9360 14338,9454 14312,9480 v1(14312,9552.46) ; U1.P1@14984.27,9376.72 14984.27,9502.27 15006,9524 v1(15006,9556)
  BOTTOM w5.5: v1(13702,9364) 13722,9384 13755,9384 13802,9431 13927,9431 13933.3,9437.3 13933.3,9444.3 13927.57,9450.02 13927.57,9457.02 13932.23,9461.69 13939.23,9461.69 13944.96,9455.96 13951.96,9455.96 13956.63,9460.63 13956.63,9467.63 13950.9,9473.36 13950.9,9480.36 13955.57,9485.02 13962.57,9485.02 13968.3,9479.3 13975.3,9479.3 13979.96,9483.96 13979.96,9490.96 13974.24,9496.69 13974.24,9503.69 13978.9,9508.36 13985.9,9508.36 13991.63,9502.63 13998.63,9502.63 14017,9521 14280.54,9521 v1(14312,9552.46) 14330.43,9570.88 14426.88,9570.88 14447,9591 14628,9591 14644,9607 14955,9607 v1(15006,9556)
A10: U1.P2 U16.22 U20.6 | length 2966.2
  TOP w5.5: U20.6@13730.95,9536.89 13730.95,9455.95 13720.69,9445.69 13720.69,9438.69 13733.49,9425.89 13733.49,9418.89 13728.82,9414.22 13721.82,9414.22 13709.02,9427.02 13702.02,9427.02 13692,9417 13674.7,9417 13669.75,9412.05 13669.75,9393.95 13664.8,9389 13658.2,9389 13653.25,9393.95 13653.25,9412.05 13648.3,9417 13617,9417 13605,9405 13605,9392.7 13609.95,9387.75 13630.05,9387.75 13635,9382.8 13635,9376.2 13630.05,9371.25 13609.95,9371.25 13605,9366.3 13605,9352 13614.15,9342.85 13621.15,9342.85 13635.37,9357.06 13642.37,9357.06 13647.03,9352.39 13647.03,9345.39 13632.82,9331.18 13632.82,9324.18 13659,9298 13678,9298 13683,9303 13683,9316.3 13678.05,9321.25 13663.95,9321.25 13659,9326.2 13659,9332.8 13663.95,9337.75 13678.05,9337.75 13683,9342.7 13683,9370 13693,9380 13693,9390 13699,9396 13720,9396 13731,9385 v1(13731,9364) ; v1(14363,9552.46) 14393.54,9552.46 14404,9542 14404,9438 14384,9418 14384,9384 14403,9365 14506,9365 14538.97,9397.97 U16.22@14569.47,9397.97 ; v1(14978,9558) 14978,9525 14968.52,9515.52 14968.52,9360.97 U1.P2@14984.27,9345.22
  BOTTOM w5.5: v1(13731,9364) 13758,9364 13811,9417 13936,9417 13981,9462 14008,9462 14011,9465 14011,9473 14004,9480 14004,9485 14009,9490 14030.3,9490 14035.25,9494.95 14035.25,9504.05 14040.2,9509 14046.8,9509 14051.75,9504.05 14051.75,9494.95 14056.7,9490 14063.3,9490 14068.25,9494.95 14068.25,9504.05 14073.2,9509 14079.8,9509 14084.75,9504.05 14084.75,9494.95 14089.7,9490 14096.3,9490 14101.25,9494.95 14101.25,9504.05 14106.2,9509 14112.8,9509 14117.75,9504.05 14117.75,9494.95 14122.7,9490 14147,9490 14158,9501 14300,9501 14318,9519 14318,9535 14333,9550 14339,9550 14343,9546 14343,9531 14349,9525 14358,9525 14363,9530 v1@14363,9551 ; v1@14363.73,9551.73 v1@14363,9551 ; v1(14978,9558) 14950,9558 14945,9563 14945,9576 14934,9587 14922,9587 14911,9576 14903.7,9576 14898.75,9580.95 14898.75,9589.05 14893.8,9594 14887.2,9594 14882.25,9589.05 14882.25,9580.95 14877.3,9576 14870.7,9576 14865.75,9580.95 14865.75,9589.05 14860.8,9594 14854.2,9594 14849.25,9589.05 14849.25,9580.95 14844.3,9576 14455,9576 14431.46,9552.46 v1(14363,9552.46) v1@14363,9551
A11: U1.P3 U16.35 U20.5 | length 3025
  TOP w5.5: v1@13750.64,9216.64 v1(13749,9215) 13713,9251 13713,9319 13750.64,9356.64 U20.5@13750.64,9536.89 ; U16.35@14128.53,9334.98 14178.98,9334.98 14182,9338 14182,9356 14190,9364 14210,9364 14219.5,9354.5 14219.5,9345.5 14210,9336 14210,9324 14213,9321 14241,9321 14254.98,9334.98 14286.02,9334.98 14294,9327 14294,9310 14288.02,9304.02 v1(14253,9304.02) ; v1(14968.52,9329.47) U1.P3@14984.27,9313.72
  BOTTOM w5.5: v1(13749,9215) 13739,9205 13657,9205 13650,9198 13650,9171 13659,9162 13673.3,9162 13678.25,9166.95 13678.25,9183.05 13683.2,9188 13689.8,9188 13694.75,9183.05 13694.75,9166.95 13699.7,9162 13706.3,9162 13711.25,9166.95 13711.25,9183.05 13716.2,9188 13722.8,9188 13727.75,9183.05 13727.75,9166.95 13732.7,9162 13751.3,9162 13756.25,9166.95 13756.25,9191.05 13761.2,9196 13767.8,9196 13772.75,9191.05 13772.75,9166.95 13777.7,9162 13784.3,9162 13789.25,9166.95 13789.25,9191.05 13794.2,9196 13800.8,9196 13805.75,9191.05 13805.75,9166.95 13810.7,9162 13817.3,9162 13822.25,9166.95 13822.25,9191.05 13827.2,9196 13833.8,9196 13838.75,9191.05 13838.75,9166.95 13843.7,9162 13850.3,9162 13855.25,9166.95 13855.25,9191.05 13860.2,9196 13866.8,9196 13871.75,9191.05 13871.75,9166.95 13876.7,9162 13886,9162 13892,9168 13892,9195 13897,9200 13905,9200 13910,9195 13910,9177 13916.46,9170.54 13922.54,9170.54 13955,9203 13997,9203 14009,9191 14038,9191 14050,9203 14068,9203 14089.33,9181.67 14096.33,9181.67 14113.38,9198.71 14120.38,9198.71 14125.04,9194.04 14125.04,9187.04 14108,9170 14108,9163 14118,9153 14171,9153 14178,9160 14178,9169 14170,9177 14158,9177 14145,9190 14145,9224 14207,9286 14234.98,9286 v1(14253,9304.02) 14271.02,9304.02 14300,9333 14482,9333 14492.41,9343.41 14492.41,9350.41 14486.68,9356.14 14486.68,9363.14 14491.35,9367.8 14498.35,9367.8 14504.08,9362.08 14511.08,9362.08 14515.74,9366.74 14515.74,9373.74 14510.01,9379.47 14510.01,9386.47 14514.68,9391.14 14521.68,9391.14 14527.41,9385.41 14534.41,9385.41 14539.08,9390.08 14539.08,9397.08 14533.35,9402.81 14533.35,9409.81 14538.02,9414.47 14545.02,9414.47 14550.74,9408.74 14557.74,9408.74 14584,9435 14862.99,9435 14871.31,9426.68 14871.31,9407.69 14876,9403 14895,9403 14899.77,9398.22 14899.77,9391.22 14886.97,9378.42 14886.97,9371.42 14891.64,9366.75 14898.64,9366.75 14911.44,9379.55 14918.44,9379.55 14923.11,9374.88 14923.11,9367.88 14910.31,9355.09 14910.31,9348.09 14914.98,9343.42 14921.98,9343.42 14934.78,9356.22 14941.78,9356.22 v1(14968.52,9329.47)
A12: U1.N4 U16.36 U20.4 | length 3193.6
  TOP w5.5: U20.4@13770.32,9536.89 13770.32,9355.32 13732,9317 13732,9252 13749,9235 13783,9235 13803,9255 13836.3,9255 13841.25,9250.05 13841.25,9219.95 13846.2,9215 13852.8,9215 13857.75,9219.95 13857.75,9250.05 13862.7,9255 13877,9255 13883,9249 13883,9213 13873,9203 13873,9185 13883,9175 13883,9166 13874,9157 13874,9126 13864,9116 13849.7,9116 13844.75,9120.95 13844.75,9161.05 13839.8,9166 13833.2,9166 13828.25,9161.05 13828.25,9120.95 13823.3,9116 13816.7,9116 13811.75,9120.95 13811.75,9161.05 13806.8,9166 13800.2,9166 13795.25,9161.05 13795.25,9120.95 13790.3,9116 13774.7,9116 13769.75,9120.95 13769.75,9151.05 13764.8,9156 13758.2,9156 13753.25,9151.05 13753.25,9120.95 13748.3,9116 13741.7,9116 13736.75,9120.95 13736.75,9141.05 13731.8,9146 13725.2,9146 13720.25,9141.05 13720.25,9120.95 13715.3,9116 13708.7,9116 13703.75,9120.95 13703.75,9141.05 13698.8,9146 13692.2,9146 13687.25,9141.05 13687.25,9120.95 13682.3,9116 13667,9116 13656,9127 13656,9154 13667,9165 13739,9165 v1(13790,9216) ; U16.36@14128.53,9303.48 14177.3,9303.48 14182.25,9308.43 14182.25,9316.53 14187.2,9321.48 14193.8,9321.48 14198.75,9316.53 14198.75,9308.43 14203.7,9303.48 v1(14214.54,9303.48) ; v1(15000.02,9297.98) 15000.02,9271.98 15005,9267 15012,9267 15015.76,9270.76 U1.N4@15015.76,9282.23
  BOTTOM w5.5: v1(13790,9216) 14108,9216 14195.48,9303.48 v1(14214.54,9303.48) 14233.06,9322 14266,9322 14295,9351 14455,9351 14553,9449 14871,9449 14883.92,9436.08 14890.92,9436.08 14906.54,9451.71 14913.54,9451.71 14918.21,9447.04 14918.21,9440.04 14902.58,9424.42 14902.58,9417.42 14907.25,9412.75 14914.25,9412.75 14929.88,9428.38 14936.88,9428.38 14941.55,9423.71 14941.55,9416.71 14925.92,9401.08 14925.92,9394.08 14930.59,9389.41 14937.59,9389.41 14953.21,9405.04 14960.21,9405.04 14964.88,9400.37 14964.88,9393.37 14949.25,9377.75 14949.25,9370.75 14953.92,9366.08 14960.92,9366.08 14976.55,9381.71 14983.55,9381.71 14988.21,9377.04 14988.21,9370.04 14972.59,9354.41 14972.59,9347.41 14984.27,9335.73 14984.27,9302.73 14989.02,9297.98 v1(15000.02,9297.98)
